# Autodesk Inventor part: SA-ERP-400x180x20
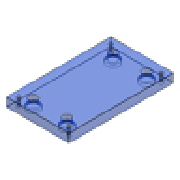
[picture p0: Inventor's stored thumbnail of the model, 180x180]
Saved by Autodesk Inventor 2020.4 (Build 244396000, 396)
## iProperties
Created: 2019-01
Part Number: SA-ERP-400x180x20
Material: S 55 C
Description: Ejector Retainer Plate
Document SubType Name: Modeling
Designer: mel
Standard Revision: 1
Manufacturer: FUTABA
Language: fr-FR
Size Designation: 400x180x20
Categories: <MemberInstance><Categories><Category DisplayName="Moule" InternalName="349578f2-f4d4-4954-8c09-8e99297a61c0" Mnemonic="MOLD"><Category DisplayName="Plaque de m
Density: 7.85 g/cm^3
Appearance: Clear - Blue
IsCustomPart: 1
Author: mel
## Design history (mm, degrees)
sketch "Sketch1"
  geometry: L1 (-90, 200)-(90, 200); L2 (90, 200)-(90, -200); L3 (90, -200)-(-90, -200); L4 (-90, -200)-(-90, 200); 5 further points
  constraints: 8 end point, 2 midpoint, 2 parallel, 1 horizontal, 1 horizontal alignment, 1 perpendicular, 1 vertical alignment
  dimensions: "d84" = 180 distance between parallel lines of L2 L4 (= W_); "d85" = 400 distance between parallel lines of L3 L1 (= L); "d86" = 78 horizontal distance of point (0, 0) point (-78, 188) (= 0.5 x S2_W); "d87" = 188 vertical distance of point (0, 0) point (-78, 188) (= 0.5 x S2_L); "d88" = 67 horizontal distance of point (0, 0) point (-67, 170) (= 0.5 x RP_W); "d89" = 170 vertical distance of point (0, 0) point (-67, 170) (= 0.5 x RP_L)
extrude "Extrusion1" new body sketch "Sketch1" distance "d20" = 20 (= H_); taper "d30" = 0 deg
hole "Hole1" sketch "Sketch1" diameter "d90" = 8.376; stored, may be unused: countersink angle "d94" = 90 deg, drill point angle "d96" = 0 deg; dims "d91" = 6, "d92" = 4, "d93" = 2, "d95" = 20 (= H_)
pattern_linear "Rectangular Pattern1" dims "d99" = 376 (computed from S2_L, Nl), "d102" = 156 (computed from S2_W, Nw)
hole "Hole2" sketch "Sketch1" diameter "d103" = 20 (= RP_d1); stored, may be unused: countersink angle "d107" = 90 deg, drill point angle "d109" = 0 deg; dims "d104" = 6, "d105" = 26 (= RP_d2), "d106" = 4 (= RP_k), "d108" = 20 (= H_)
pattern_linear "Rectangular Pattern2" dims "d112" = 340 (computed from RP_L, Nl), "d115" = 134 (computed from RP_W, Nw)
chamfer "Chamfer1" distance "d116" = 0.5; stored, may be unused: second distance "d117" = 2, angle "d118" = 45 deg
body "Solid1"
other parameters: "L" = 400 [user parameter; used in 1 equation term], "W_" = 180 [user parameter; used in 1 equation term], "H_" = 20 [user parameter; used in 3 equation terms], "S2_W" = 156 [user parameter; used in 2 equation terms], "S2_L" = 376 [user parameter; used in 2 equation terms], "RP_k" = 4 [user parameter; used in 1 equation term], "RP_d1" = 20 [user parameter; used in 1 equation term], "RP_d2" = 26 [user parameter; used in 1 equation term], "RP_W" = 134 [user parameter; used in 2 equation terms]
